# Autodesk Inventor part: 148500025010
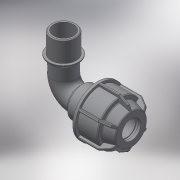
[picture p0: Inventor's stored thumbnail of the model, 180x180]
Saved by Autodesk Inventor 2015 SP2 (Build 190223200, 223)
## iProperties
Created: 2017-08
Part Number: 148500025010
Material: Generic
Description: PLASSON L.14 90° ELBOW MALE ADAPTOR (SILVER) 25-1"
Document SubType Name: Modeling
Designer: KIM
Density: 1 g/cm^3
Appearance: Default
Author: KIM
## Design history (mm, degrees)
derived "148500.ipt"
feature "Solid1::148500.ipt"
feature "Solid2::148500.ipt"
tag "TaggingFeature1"
body "Solid1"
body "Solid2"
other parameters: "d1" = 25, "d2" = 47, "d4" = 15 deg, "d5" = 31.02, "d6" = 10.2366, "d16" = 25.5, "d17" = 2.35, "d24" = 2.35, "d25" = 45, "d26" = 37.5, "d27" = 2.35, "d28" = 135 deg, "d29" = 1.41, "d31" = 1.25, "d46" = 150 deg, "d49" = 2.5, "d50" = 0, "d58" = 0.75, "d61" = 360 deg, "d63" = 23.75, "d94" = 49, "d96" = 36.5739, "d97" = 19, "d98" = 23.2743, "d99" = 31.08782, "d100" = 135 deg, "d108" = 1.25, "d112" = 24.7, "d113" = 62, "d114" = 47.94, "d115" = 31.08782, "d116" = 45 deg, "d117" = 0, "d118" = 0, "d119" = 33.249, "d120" = 19, "d121" = 39.8988, "d122" = 19.95, "d123" = 1, "d_" = 25, "R_" = 33.249, "A_" = 62, "l_" = 47, "l_2" = 19, "A_1" = 49
